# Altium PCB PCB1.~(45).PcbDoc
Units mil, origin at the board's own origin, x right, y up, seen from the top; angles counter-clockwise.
Board outline 6000 x 4000 mil, 2 copper layers (Top Layer, Bottom Layer); 37 components, 28 nets, 157 pads, 81 vias.
Unrouted connection lines stored in the file: 73.
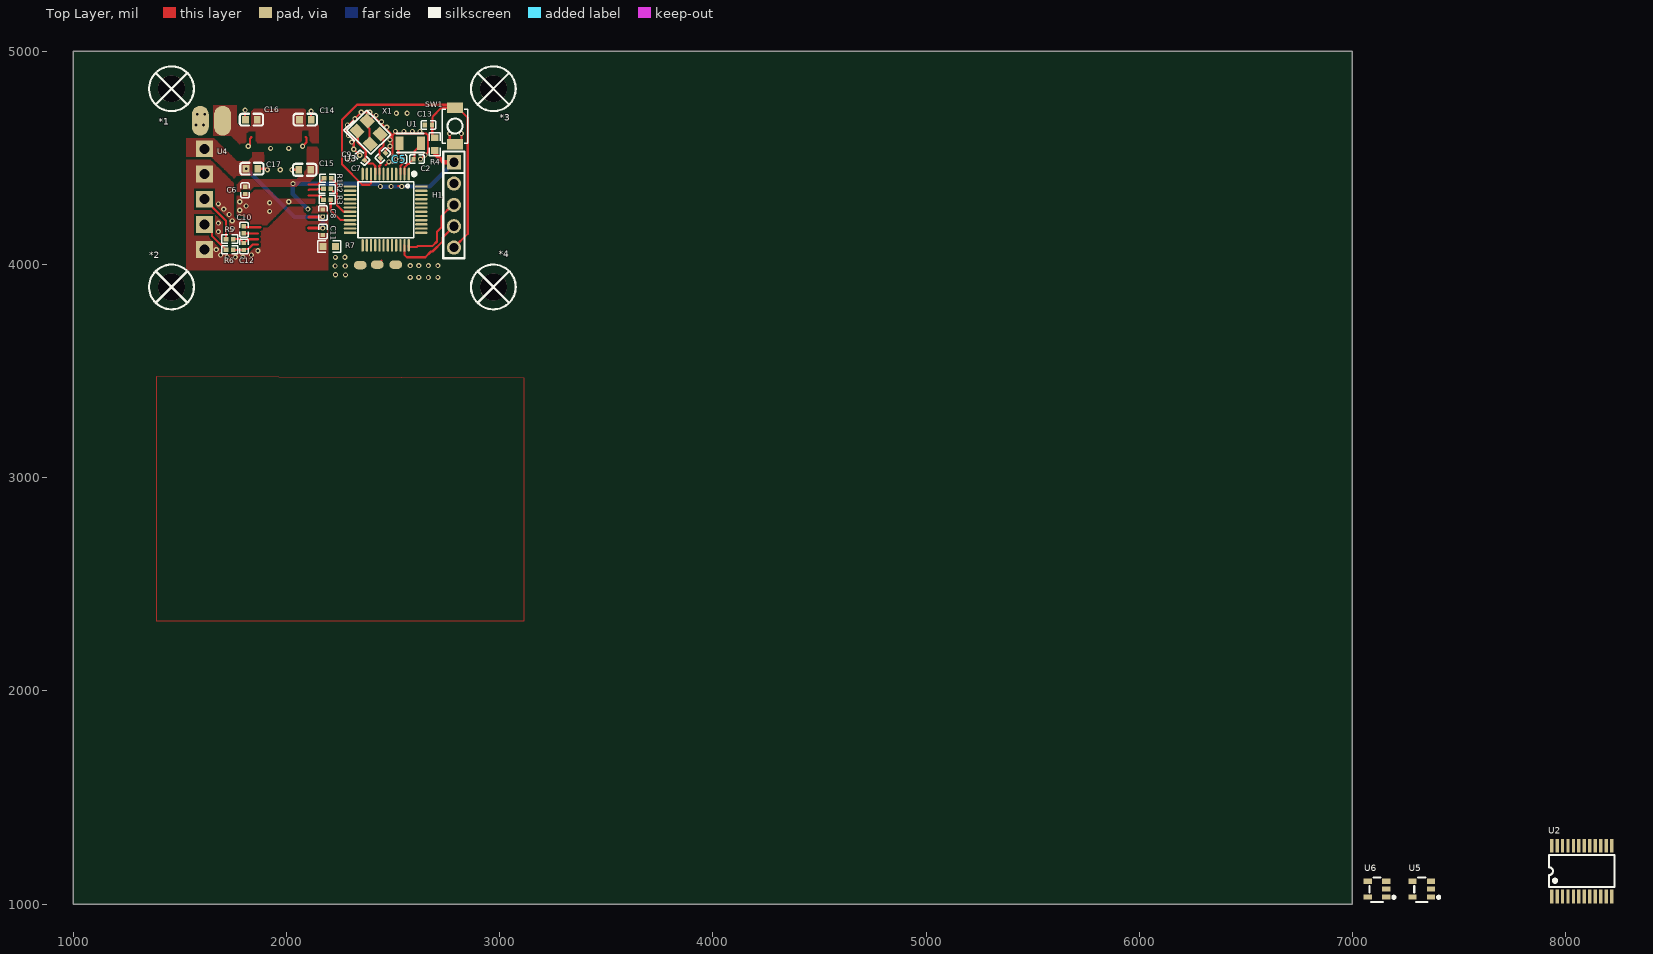
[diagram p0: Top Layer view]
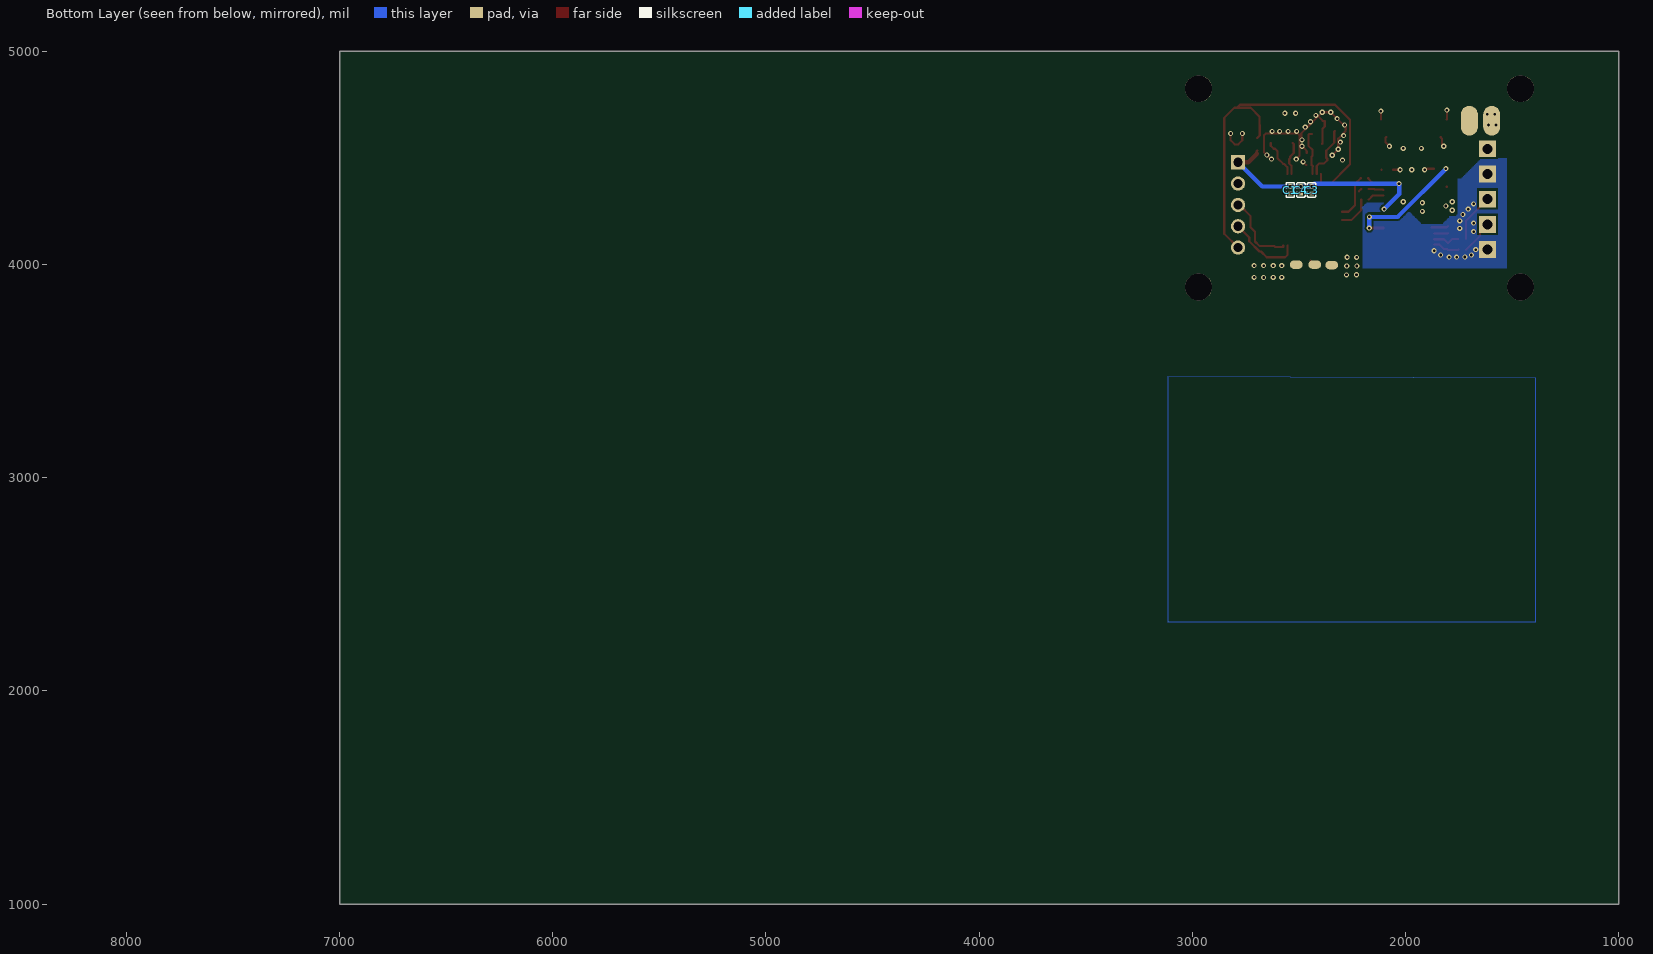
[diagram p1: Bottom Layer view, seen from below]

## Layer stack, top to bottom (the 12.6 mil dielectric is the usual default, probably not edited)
Top Solder: solder mask 0.4, Solder Resist, Dk 3.5
Top Layer: signal copper 1.4
Dielectric 1: dielectric 12.6, FR-4, Dk 4.8
Bottom Layer: signal copper 1.4
Bottom Solder: solder mask 0.4, Solder Resist, Dk 3.5

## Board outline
1000,1000 7000,1000 7000,5000 1000,5000

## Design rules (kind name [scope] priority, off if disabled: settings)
Clearance [All] p1: gap=8 ignorepadtopadclearanceinfootprint=FALSE
ComponentClearance [All] p1: gap=0 collisioncheckmode=3 verticalgap=0 showdistances=FALSE
HoleSize [All] p1: absolutevalues=TRUE maxlimit=130 minlimit=1 maxpercent=80.000 minpercent=20.000
MinimumSolderMaskSliver [All] p1: minsoldermaskwidth=4
PlaneConnect [All] p1: planeconnectstyle=Direct reliefexpansion=20 reliefentries=4 reliefconductorwidth=10 reliefairgap=10
PolygonConnect [All] p1: connectstyle=Direct reliefconductorwidth=10 reliefentries=4 polygonreliefangle="90 Angle" airgapwidth=10
RoutingVias [All] p1: holewidth=28 width=50 viastyle="Through Hole" minholewidth=28 minwidth=50 maxholewidth=28 maxwidth=50
SilkToSilkClearance [All] p1: silktosilkclearance=2
SilkToSolderMaskClearance [IsPad] p1: minsilkscreentomaskgap=2 clearancetoexposedcopper=TRUE
SolderMaskExpansion [All] p1: expansion=0 istentingtop=FALSE
SupplyNets "Schematic Supply Nets_2" [InNet('6V')] p1: voltage=0.000
SupplyNets "Schematic Supply Nets" [InNet('3V3')] p2: voltage=0.000
SupplyNets "Schematic Supply Nets_4" [InNet('5V')] p3: voltage=0.000
SupplyNets "Schematic Supply Nets_3" [InNet('DGND')] p4: voltage=0.000
SupplyNets "Schematic Supply Nets_1" [InNet('AGND')] p5: voltage=0.000
Width [All] p1: maxlimit=50 minlimit=10 preferedwidth=10
24 further rules are at their usual default settings.

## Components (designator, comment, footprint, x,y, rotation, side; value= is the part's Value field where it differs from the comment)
*1 "螺丝孔_1" M3螺丝 1460,4825 r0 top
*2 "螺丝孔_1" M3螺丝 1460,3895 r0 top
*3 "螺丝孔_1" M3螺丝 2970,4825 r0 top
*4 "螺丝孔_1" M3螺丝 2970,3895 r0 top
C1 "cc0402krx7r7bb104" C0402 2540,4350 r270 bottom value=100nF
C2 "cc0402jrnpo9bn220" C0402 2611.54,4495 r180 top value=22pF
C3 "cc0402krx7r7bb104" C0402 2440,4350 r270 bottom value=100nF
C4 "cc0402krx7r7bb104" C0402 2490,4350 r90 bottom value=100nF
C5 "cc0402jrnpo9bn220" C0402 2528.46,4495 r0 top value=22pF
C6 "cc0402krx7r7bb104" C0402 1805,4348.46 r270 top value=100nF
C7 "cc0402jrnpo9bn180" C0402 2451.7,4511.7 r45 top value=18pF
C8 "cc0402krx7r7bb104" C0402 2170,4241.54 r90 top value=100nF
C9 "cc0402jrnpo9bn180" C0402 2354.68,4501.29 r315 top value=18pF
C10 "cc0402krx7r7bb104" C0402 1800,4163.46 r90 top value=100nF
C11 "gcm155r71h103ka55d" C0402 2170,4155 r270 top value=10nF
C12 "gcm155r71h103ka55d" C0402 1800,4085 r270 top value=10nF
C13 "cc0402krx7r7bb104" C0402 2665,4655 r0 top value=100nF
C14 "cga0603x5r105k500jt" C0603 2087.56,4680 r0 top value=1uF
C15 "cga0603x5r105k500jt" C0603 2085,4445 r180 top value=1uF
C16 "cga0603x5r105k500jt" C0603 1835,4680 r180 top value=1uF
C17 "cga0603x5r105k500jt" C0603 1837.44,4450 r0 top value=1uF
H1 "pz254v-11-05p" HDR-TH_5P-P2.54-V-M 2785,4280 r270 top
R1 "frc0402f47r0ts" R0402 2192.04,4405 r0 top value=47Ω
R2 "frc0402f47r0ts" R0402 2190,4355 r0 top value=47Ω
R3 "frc0402f47r0ts" R0402 2190,4305 r0 top value=47Ω
R4 "frc0603f1002ts" R0603 2695,4565 r270 top value=10kΩ
R5 "frc0402f1000ts" R0402 1732.96,4120 r0 top value=100Ω
R6 "frc0402f1000ts" R0402 1732.96,4070 r0 top value=100Ω
R7 "0603waf0000t5e" R0603 2200,4085 r0 top value=0Ω
SW1 "ts-1088-ar02016" SW-SMD_L3.9-W3.0-P4.45 2790,4650 r90 top
U1 "fc31m2-32.768-ntlnndtl" CRYSTAL-SMD_L3.2-W1.5 2580,4570 r0 top value=32.768kHz
U2 "ads1232ipwr" TSSOP-24_L7.8-W4.4-P0.65-LS6.4-BL 8075,1155 r0 top
U3 "stm32g031c8t6" LQFP-48_L7.0-W7.0-P0.50-LS9.0-BL 2464.84,4257.68 r180 top
U4 "5个焊盘" 5个焊盘 1615,4543.1 r270 top
U5 "tps7a2033pdbvr" SOT-23-5_L2.9-W1.6-P0.95-LS2.8-BR 7325,1070 r0 top
U6 "tps7a2050pdbvr" SOT-23-5_L2.9-W1.6-P0.95-LS2.8-BR 7115,1070 r0 top
X1 "x32258mob4si" CRYSTAL-SMD_4P-L3.2-W2.5-BL 2385,4620 r315 top value=8MHz

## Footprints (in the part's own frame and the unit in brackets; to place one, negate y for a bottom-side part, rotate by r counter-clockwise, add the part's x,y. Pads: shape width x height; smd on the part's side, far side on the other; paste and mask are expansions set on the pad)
5个焊盘 [mm]
  rect 2x2 hole 1.2: 1(0,0) 2(3,0) 3(6.001,0) 4(9,0) 5(12,0)
C0402 [mm]
  rect 0.5x0.54 smd: 1(-0.42,0) 2(0.42,0)
  silkscreen extent -0.87,-0.5 0.87,0.5
C0603 [mm]
  rect 0.8x0.9 smd: 1(-0.7,0) 2(0.7,0)
  silkscreen extent -1.39,-0.71 1.39,0.71
CRYSTAL-SMD_4P-L3.2-W2.5-BL [mm]
  rect 1.4x1.2 smd: 1(-1.1,-0.85) 2(1.1,-0.85) 3(1.1,0.85) 4(-1.1,0.85)
  silkscreen extent -2.26,-1.91 2.03,1.68
CRYSTAL-SMD_L3.2-W1.5 [mm]
  rect 0.95x1.6 smd: 1(-1.308,0) 2(1.308,0)
  silkscreen extent -1.6,-1.14 1.6,1.14
HDR-TH_5P-P2.54-V-M [mm]
  rect 1.7x1.7 hole 1.1: 1(-5.08,0)
  round 1.7 hole 1.1: 2(-2.54,0) 3(0,0) 4(2.54,0) 5(5.08,0)
  silkscreen extent -6.35,-1.27 6.35,1.27
LQFP-48_L7.0-W7.0-P0.50-LS9.0-BL [mm]
  oval 0.27x1.5 smd paste+0 mask+0.05: 1(-2.75,-4.25) 2(-2.25,-4.25) 3(-1.75,-4.25) 4(-1.25,-4.25) 5(-0.75,-4.25) 6(-0.25,-4.25) 7(0.25,-4.25) 8(0.75,-4.25) 9(1.25,-4.25) 10(1.75,-4.25) 11(2.25,-4.25) 12(2.75,-4.25) 25(2.75,4.25) 26(2.25,4.25) 27(1.75,4.25) 28(1.25,4.25) 29(0.75,4.25) 30(0.25,4.25) 31(-0.25,4.25) 32(-0.75,4.25) 33(-1.25,4.25) 34(-1.75,4.25) 35(-2.25,4.25) 36(-2.75,4.25)
  oval 1.5x0.27 smd paste+0 mask+0.05: 13(4.25,-2.75) 14(4.25,-2.25) 15(4.25,-1.75) 16(4.25,-1.25) 17(4.25,-0.75) 18(4.25,-0.25) 19(4.25,0.25) 20(4.25,0.75) 21(4.25,1.25) 22(4.25,1.75) 23(4.25,2.25) 24(4.25,2.75) 37(-4.25,2.75) 38(-4.25,2.25) 39(-4.25,1.75) 40(-4.25,1.25) 41(-4.25,0.75) 42(-4.25,0.25) 43(-4.25,-0.25) 44(-4.25,-0.75) 45(-4.25,-1.25) 46(-4.25,-1.75) 47(-4.25,-2.25) 48(-4.25,-2.75)
  silkscreen extent -3.59,-4.46 3.3,3.34
M3螺丝 [mil]
  round 126 hole 126 paste-99999 mask+4: 1(0,0)
  silkscreen extent -105,-105 105,105
R0402 [mm]
  rect 0.566x0.54 smd paste-100 mask+0.051: 1(-0.433,0) 2(0.433,0)
  silkscreen extent -0.94,-0.5 0.94,0.5
R0603 [mil]
  rect 31.75x34.02 smd paste-3937.01 mask+2: 1(-29.66,0) 2(29.66,0)
  silkscreen extent -55,-26 55,26
SOT-23-5_L2.9-W1.6-P0.95-LS2.8-BR [mm]
  rect 1x0.6 smd paste+0 mask+0.05: 1(1.1,-0.95) 2(1.1,0) 3(1.1,0.95) 4(-1.1,0.95) 5(-1.1,-0.95)
  silkscreen extent -0.89,-1.52 2.16,1.4
SW-SMD_L3.9-W3.0-P4.45 [mm]
  rect 1.23x1.86 smd: 1(-2.185,0) 2(2.185,0)
  silkscreen extent -2.03,-1.54 2.03,1.54
TSSOP-24_L7.8-W4.4-P0.65-LS6.4-BL [mm]
  rect 0.4x1.65 smd: 1(-3.575,-3.023) 2(-2.925,-3.023) 3(-2.275,-3.023) 4(-1.625,-3.023) 5(-0.975,-3.023) 6(-0.325,-3.023) 7(0.325,-3.023) 8(0.975,-3.023) 9(1.625,-3.023) 10(2.275,-3.023) 11(2.925,-3.023) 12(3.575,-3.023) 13(3.575,3.023) 14(2.925,3.023) 15(2.275,3.023) 16(1.625,3.023) 17(0.975,3.023) 18(0.325,3.023) 19(-0.325,3.023) 20(-0.975,3.023) 21(-1.625,3.023) 22(-2.275,3.023) 23(-2.925,3.023) 24(-3.575,3.023)
  silkscreen extent -3.89,-1.91 3.94,1.91

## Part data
C1 C3 C4 C6 C8 C10 C13: "容值:100nF;精度:±10%;额定电压:16V;温度系数:X7R;", JLCPCB Part Class="Extended Part", LCSC Part Name="100nF ±10% 16V", Manufacturer=YAGEO(国巨), ManufacturerPart=CC0402KRX7R7BB104, Temperature Coefficient=X7R, Tolerance=±10%, Voltage Rating=16V
C2 C5: "容值:22pF;精度:±5%;额定电压:50V;温度系数:NP0;", JLCPCB Part Class="Extended Part", LCSC Part Name="22pF ±5% 50V", Manufacturer=YAGEO(国巨), ManufacturerPart=CC0402JRNPO9BN220, Temperature Coefficient=NP0, Tolerance=±5%, Voltage Rating=50V
C7 C9: "容值:18pF;精度:±5%;额定电压:50V;温度系数:NP0;", JLCPCB Part Class="Extended Part", LCSC Part Name="18pF ±5% 50V", Manufacturer=YAGEO(国巨), ManufacturerPart=CC0402JRNPO9BN180, Temperature Coefficient=NP0, Tolerance=±5%, Voltage Rating=50V
C11 C12: "容值:10nF;精度:±10%;额定电压:50V;温度系数:X7R;", JLCPCB Part Class="Extended Part", LCSC Part Name="10nF ±10% 50V", Manufacturer=muRata(村田), ManufacturerPart=GCM155R71H103KA55D, Temperature Coefficient=X7R, Tolerance=±10%, Voltage Rating=50V
C14 C15 C16 C17: "容值:1uF;精度:±10%;额定电压:50V;温度系数:X5R;", JLCPCB Part Class="Extended Part", LCSC Part Name="1uF ±10% 50V 停产", Manufacturer=HRE(芯声), ManufacturerPart=CGA0603X5R105K500JT, Temperature Coefficient=X5R, Tolerance=±10%, Voltage Rating=50V
H1: "插针结构:1x5P;间距:2.54mm;行距:-;圆针/方针:方针;安装方式:直插;排数:单排;总PIN位数:5P;额定电流:3A;额定电压:250V;配合针长度:6mm;塑高:2.5mm;端接针长度:3mm;触头材质:黄铜;触头镀层:-;工作温度:-40℃~+105℃;颜色:黑色;", Color=黑色, Current Rating=3A, JLCPCB Part Class="Extended Part", LCSC Part Name="1x5P 间距:2.54mm 方针 直插", Manufacturer=XFCN(兴飞), ManufacturerPart=PZ254V-11-05P, Operating Temperature=-40℃~+105℃, Voltage Rating (Max)=250V
R1 R2 R3: "电阻类型:厚膜电阻;阻值:47Ω;精度:±1%;功率:62.5mW;工作电压:50V;温度系数:±100ppm/℃;", JLCPCB Part Class="Extended Part", LCSC Part Name="47Ω ±1% 62.5mW 厚膜电阻", Manufacturer=FOJAN(富捷), ManufacturerPart=FRC0402F47R0TS, Operating Temperature=-55℃~+155℃, Power(Watts)=62.5mW, Temperature Coefficient=±100ppm/℃, Tolerance=±1%, Voltage-Supply(Max)=50V
R4: "电阻类型:厚膜电阻;阻值:10kΩ;精度:±1%;功率:100mW;工作电压:75V;温度系数:±100ppm/℃;", JLCPCB Part Class="Extended Part", LCSC Part Name="10kΩ ±1% 100mW 厚膜电阻", Manufacturer=FOJAN(富捷), ManufacturerPart=FRC0603F1002TS, Operating Temperature=-55℃~+155℃, Power(Watts)=100mW, Temperature Coefficient=±100ppm/℃, Tolerance=±1%, Voltage-Supply(Max)=75V
R5 R6: "电阻类型:厚膜电阻;阻值:100Ω;精度:±1%;功率:62.5mW;工作电压:50V;温度系数:±100ppm/℃;", JLCPCB Part Class="Extended Part", LCSC Part Name="100Ω ±1% 62.5mW 厚膜电阻", Manufacturer=FOJAN(富捷), ManufacturerPart=FRC0402F1000TS, Operating Temperature=-55℃~+155℃, Power(Watts)=62.5mW, Temperature Coefficient=±100ppm/℃, Tolerance=±1%, Voltage-Supply(Max)=50V
R7: "电阻类型:厚膜电阻;阻值:0Ω;精度:±1%;功率:100mW;工作电压:75V;温度系数:-;", JLCPCB Part Class="Basic Part", LCSC Part Name="0Ω ±1% 100mW 厚膜电阻", Manufacturer=UNI-ROYAL(厚声), ManufacturerPart=0603WAF0000T5E, Operating Temperature=-55℃~+155℃, Power(Watts)=100mW, Temperature Coefficient=-, Tolerance=±1%, Voltage-Supply(Max)=75V
SW1: "电路结构:单刀单掷;按钮形状:圆形按钮;作用力:1.6N;安装方式:立贴;开关长度:3.9mm;开关宽度:3mm;开关高度:2mm;带支架:不带支架;触点电流:50mA;额定电压:12V;带灯:-;工作寿命:10万次;", Actuator/Cap Color=黑色, Contact Current=50mA, IP Rating=-, JLCPCB Part Class="Basic Part", LCSC Part Name="3.9*3*2mm 立贴 轻触开关", Manufacturer=XUNPU(讯普), ManufacturerPart=TS-1088-AR02016, Operating Force=1.6N, Operating Temperature=-30℃~+80℃, Voltage Rating=12V
U1: "晶振类型:贴片晶振;频率:32.768kHz;常温频差:±10ppm;负载电容:12.5pF;频率稳定度:±10ppm;", Equivalent Series Resistance(ESR)=70kΩ, Frequency Stability=±10ppm, JLCPCB Part Class="Extended Part", LCSC Part Name="3215 2P 32.768kHz 12.5pF ±10ppm -40~+85℃(±10ppm)", Load Capacitance=12.5pF, Manufacturer=HCI(杭晶), ManufacturerPart=FC31M2-32.768-NTLNNDTL, Operating Temperature=-40℃~+85℃
U2: "分辨率(位):24;采样率:10Hz;工作电压:2.7V~5.3V;接口类型:SPI;", Clock Frequency=4.9152MHz；200kHz~8MHz, JLCPCB Part Class="Extended Part", LCSC Part Name="用于桥式传感器的24bit 模数转换器", Manufacturer=TI(德州仪器), ManufacturerPart=ADS1232IPWR, Operating Temperature=-40℃~+105℃, Quiescent Current (Iq)=1.3uA, Temperature Sensors=内置, Voltage - Supply=2.7V~5.3V, Voltage Reference=外置, Voltage Reference Drift=-
U3: "CPU内核:ARM Cortex-M0+;CPU最大主频:64MHz;CPU位数:32 Bit;", JLCPCB Part Class="Extended Part", LCSC Part Name="主流Arm Cortex-M0+ MCU，具有64 KB Flash存储器、8 KB RAM、64 MHz CPU、2x USART、定时器、ADC和通信接口，1.7-3.6V", Manufacturer=ST(意法半导体), ManufacturerPart=STM32G031C8T6, Operating Temperature=-40℃~+85℃, Voltage - Supply=1.7V~3.6V
U5: "输出类型:固定;最大输入电压:6V;输出电压:3.3V;输出电流:300mA;输出极性:正极;", Dropout Voltage=140mV@(300mA), JLCPCB Part Class="Extended Part", LCSC Part Name="具有高 PSRR 的 300mA、超低噪声、低 IQ、低压降 (LDO) 线性稳压器", Manufacturer=TI(德州仪器), ManufacturerPart=TPS7A2033PDBVR, Maximum Input Voltage=6V, Operating Temperature=-40℃~+125℃@(Tj), Output Current=300mA, Output Voltage=3.3V, standby current=15uA
U6: "输出极性:正极;工作电压:6V;输出电压:5V;输出电流:300mA;电源纹波抑制比(PSRR):65dB@(100Hz);输出类型:固定;", JLCPCB Part Class="Extended Part", LCSC Part Name="800mV~5.5V 300mA 6V", Manufacturer=TI(德州仪器), ManufacturerPart=TPS7A2050PDBVR, Operating Temperature=-40℃~+125℃@(Tj), Output Current=300mA, Output Voltage=5V, Power Supply Rejection Ratio (PSRR)=65dB@(100Hz), standby current=6.5uA, Voltage - Supply=6V, Voltage Dropout=140mV@(300mA)
X1: "晶振类型:贴片晶振;频率:8MHz;常温频差:±10ppm;负载电容:12pF;频率稳定度:±20ppm;", Equivalent Series Resistance(ESR)=180Ω, Frequency Stability=±20ppm, JLCPCB Part Class="Extended Part", LCSC Part Name="YSX321SL 8MHZ 4P 3225 12PF ±10PPM -40~85℃ (±20PPM)", Load Capacitance=12pF, Manufacturer=YXC(扬兴晶振), ManufacturerPart=X32258MOB4SI, Normal temperature Frequency Tolerance=±10ppm, Operating Temperature=-40℃~+85℃

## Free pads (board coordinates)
  oval 80x140 all layers, no hole: 7(1595,4675) 7(1700,4675)
  oval 60x40 all layers, no hole: 7(2345.3,3998) 7(2425,4000) 7(2512,3999.83)

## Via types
v1: diameter 24, hole 12, Top Layer to Bottom Layer, tented both sides, 81 vias

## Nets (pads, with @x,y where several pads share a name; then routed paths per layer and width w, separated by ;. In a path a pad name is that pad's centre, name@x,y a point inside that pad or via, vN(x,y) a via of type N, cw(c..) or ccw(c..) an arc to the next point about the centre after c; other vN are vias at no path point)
3V3: C1.1 C3.1 C4.2 C6.1 C15.1 H1.1 R4.2 U2.1 U2.19 U2.20 U3.4 U3.5 U3.6 U5.5 | length 1103.6
  Top Layer w10: C6.1 C6.1@1805.79,4365 ; C15.1@2112.56,4443.03 C15.1 ; v1(2440,4366.54) v1@2442.68,4369.22 ; 2521.89,4369.22 2537.32,4369.22 v1(2540,4366.54) ; R4.2 2697.01,4533.33 R4.2@2697.01,4519.53
  Top Layer w20: R4.2@2697.01,4519.53 2736.54,4480 H1.1
  Bottom Layer w10: v1@2028.6,4378.6 v1(2030,4380) ; 2058.74,4380 2060.53,4378.21
  Bottom Layer w20: v1@2028.6,4378.6 2028.6,4331.4 v1(2100,4260) ; v1@2030.11,4379.89 2426.18,4379.89 C3.1@2439.37,4366.7 ; C3.1@2440.69,4365.85 C4.2@2489.31,4365.85 ; C4.2@2490.63,4366.49 C1.1@2539.37,4366.49 ; v1(2540,4366.54) 2671.54,4366.54 H1.1
  other v1: 2490,4366.54
5V: C8.1 C11.1 C17.1 U2.16 U2.18 U4.1 U6.5 | length 638.5
  Top Layer w10: 2104,4171.02 2104.26,4171.28 ; 2104,4222.21 2105.39,4223.6 ; v1(2168.61,4223.6) C8.1 ; v1(2169.74,4171.28) C11.1
  Top Layer w15: 2104.26,4171.28 v1(2169.74,4171.28) ; 2105.39,4223.6 v1(2168.61,4223.6)
  Bottom Layer w10: v1(2168.61,4223.6) v1@2169.17,4223.04 ; v1@2169.17,4171.85 v1(2169.74,4171.28)
  Bottom Layer w20: v1(1810,4450) 2036.39,4223.6 v1(2168.61,4223.6) ; v1@2169.17,4171.85 v1@2169.17,4223.04
6V: C14.1 C16.1 pad.7@1700,4675 U5.1 U5.3 U6.1 U6.3
AGND: C8.2 C11.2 R7.1 U2.13 U2.14 U2.15 U2.17 U4.2 U4.5
  other v1: 1760,4035 1795,4035 1720.87,4035.63 1690,4045 1835,4045 1865,4065 1670,4070 1680,4155 1745,4170 1680,4195 1745,4205 1730,4235 1705,4260 1680,4285
AINN1: R6.1 U4.4 | length 160.9
  Top Layer w10: U4.4 1649.37,4154.39 1649.37,4136.04 1715.41,4070 R6.1
AINP1: R5.1 U4.3 | length 228.7
  Top Layer w10: U4.3 1715.92,4205.94 R5.1
DGND: C1.2 C2.1 C3.2 C4.1 C5.1 C6.2 C7.2 C9.1 C13.1 C14.2 C15.2 C16.2 C17.2 H1.2 pad.7@1595,4675 pad.7@2345.3,3998 R7.2 SW1.1 U2.2 U2.3 U2.4 U2.5 U2.6 U2.7 U2.8 U2.21 U3.7 U5.2 U6.2 X1.2 X1.4 | length 1384
  Top Layer w10: v1(1805,4725) 1805,4682.44 C16.2 ; C17.2 1901.21,4450 1906.21,4445 v1(1910,4445) ; v1(2025,4445) C15.2 ; v1(2115,4720) 2115.12,4719.88 C14.2 ; v1(2342.98,4512.98) v1(2315,4540.96) 2315,4590.88 2281.52,4624.36 2281.52,4633.48 2280,4635 2280,4645 v1(2350,4715) v1(2390,4715) v1@2409.14,4695.86 ; X1.2 2389.18,4568.5 2389.18,4636.81 2378.04,4647.95 X1.4 2387.57,4674.29 v1@2409.14,4695.86 ; C7.2 2462.83,4523.95 2462.83,4530.8 2463.39,4531.35 2463.39,4533.39 v1(2485,4555) ; v1(2485,4585) 2487.68,4587.68 2487.68,4604.07 2488.48,4604.87 2488.48,4615.64 2457.06,4647.06 2457.06,4647.94 v1@2409.14,4695.86 ; v1(2511.92,4495) 2511.92,4495.79 2496.8,4510.91 2496.8,4606.88 2505.36,4615.44 2649.41,4615.44 2650.35,4614.5 2655.59,4614.5 2663.2,4606.88 2663.2,4527.61 v1(2649.71,4514.12) 2636.22,4500.63 2632.92,4500.63 C2.1@2628.08,4495.79 ; v1(2765,4615) 2765,4583.19 2784.21,4563.98 SW1.1 2800.79,4563.98 2820,4583.19 v1(2820,4615)
  other v1: 2580,3940 2620,3940 2665.24,3939.54 2710,3940 2229.44,3952.22 2276.16,3951.9 2227.87,3993.61 2274.91,3993.61 2580,3995 2620,3995 2665,3995 2710,3995 2228.81,4034.06 2273.34,4034.38 1920,4250 1780,4255 1810,4275 1920,4290 1780,4295 2010,4295 1970,4445 2295,4490 2628.08,4495 1925,4545 2010,4545 2305,4575 2290,4605 2510,4625 2550,4625 2590,4625 2625,4625 2470,4645 1575,4655 1610,4655 2285,4655 2445,4670 2320,4685 2420,4700 1580,4705 1615,4705 2515,4710 2565,4710
DOUT: R1.2 U3.19 | length 211.9
  Top Layer w10: R1.2 2209.59,4405 2236.17,4378.41 2236.17,4278.76 2266.97,4247.96 2297.4,4247.96 U3.19
NetC2_2: C2.2 U1.2 U3.2 | length 183.5
  Top Layer w10: U3.2 2553.54,4425.12 2553.54,4456.49 2569.61,4472.56 2573.35,4472.56 2599.84,4499.06 2599.84,4532.3 2611.05,4543.5 2617.8,4543.5 2631.5,4557.21 U1.2
NetC5_2: C5.2 U1.1 U3.3 | length 160.6
  Top Layer w10: U1.1 2523.5,4565 2523.5,4523.5 2540.16,4506.85 2540.16,4499.84 C5.2 2545,4473.85 2533.86,4462.71 2533.86,4425.12 U3.3
NetC7_1: C7.1 U3.8 X1.3 | length 214.9
  Top Layer w10: U3.8 U3.8 2435.35,4432.44 2435.35,4459.95 2434.11,4461.19 2440.56,4467.63 2440.56,4506.29 2435.91,4510.93 2435.91,4538.56 2455.11,4557.75 2455.11,4609.54 2452.33,4612.33 2440,4612.33 X1.3
NetC9_2: C9.2 U3.9 X1.1 | length 254.5
  Top Layer w10: X1.1 2333.5,4624.18 2333.5,4572.39 2371.34,4534.54 2371.34,4501.41 2366.37,4496.44 C9.2 2381.12,4474.85 2403.69,4474.85 2415.67,4462.86 2415.67,4432.44 2415.67,4425.04 U3.9
NetC10_1: C10.1 U2.10 | length 66.6
  Top Layer w10: C10.1 1800.74,4146.18 1865.26,4146.18 1866,4145.43
NetC10_2: C10.2 U2.9 | length 78.3
  Top Layer w10: C10.2 1804.84,4175.16 1819.84,4175.16 1820,4175 1876.23,4175
NetC12_1: C12.1 R5.2 U2.11 | length 131.2
  Top Layer w10: R5.2 1780.75,4120 1799.21,4101.54 C12.1 1800.79,4101.54 1818.52,4119.27 1865.43,4119.27 1866,4119.84
NetC12_2: C12.2 R6.2 U2.12 | length 127.3
  Top Layer w10: R6.2 1750.77,4069.23 1799.23,4069.23 C12.2 1804.84,4073.3 1820.44,4073.3 1841.39,4094.26 1866,4094.26
NetR1_1: R1.1 U2.24 | length 83.4
  Top Layer w10: 2104,4375.74 2145.74,4375.74 2168.86,4398.86 2168.86,4399.37 2174.49,4405 R1.1
NetR2_1: R2.1 U2.23 | length 71
  Top Layer w10: 2104,4350.15 2106.87,4353.02 2144.85,4353.02 2146.82,4355 R2.1
NetR3_1: R3.1 U2.22 | length 77.1
  Top Layer w10: 2104,4324.56 2152.89,4324.56 2172.45,4305 R3.1
NRST: C13.2 H1.5 R4.1 SW1.2 U3.10 | length 1940.1
  Top Layer w10: U3.10 2396.06,4424.88 2396.06,4384.31 2396.1,4384.27 2394.62,4382.79 2394.62,4381.29 2388.25,4374.91 2355.11,4374.91 2260,4470.02 2260,4679.63 2330.22,4749.85 2776.17,4749.85 SW1.2 ; C13.2 C13.2@2681.54,4655.79 ; R4.1 2693.87,4594.66 2682.99,4605.54 2682.99,4652.99 2685,4655 2685,4695 2726.02,4736.02 SW1.2 ; H1.5 2850,4145 2850,4688.42 2802.4,4736.02 SW1.2
PDWN: R3.2 U3.21 | length 159.4
  Top Layer w10: R3.2 2207.04,4255.66 2254.11,4208.59 2297.4,4208.59 U3.21
SCLK: R2.2 U3.20 | length 15.5
  Top Layer w10: R2.2 2207.55,4355 R2.2@2218.17,4344.37
SWCLK: H1.3 U3.36 | length 359.3
  Top Layer w10: U3.36 2573.11,4082.84 2573.27,4082.68 2610.66,4082.68 2615.66,4087.68 2685.04,4087.68 2705.45,4108.09 2705.45,4153.76 2725.86,4174.17 2725.86,4227.64 2778.22,4280 H1.3
SWDIO: H1.4 U3.35 | length 352.4
  Top Layer w10: U3.35 2553.3,4090.24 2553.3,4047.61 2552.35,4046.66 2564.33,4034.67 2650.57,4034.67 2677.48,4061.59 2684.4,4061.59 2732.47,4109.65 2732.47,4127.47 H1.4
USART1_RX: pad.7@2512,3999.83 U3.32
USART1_TX: pad.7@2425,4000 U3.29
USART2_RX: U3.14
USART2_TX: U3.13
pads on no net: *1.1 *2.1 *3.1 *4.1 U3.1 U3.11 U3.12 U3.15 U3.16 U3.17 U3.18 U3.22 U3.23 U3.24 U3.25 U3.26 U3.27 U3.28 U3.30 U3.31 U3.33 U3.34 U3.37 U3.38 U3.39 U3.40 U3.41 U3.42 U3.43 U3.44 U3.45 U3.46 U3.47 U3.48 U5.4 U6.4
copper on no net: | length 164.1
  Top Layer w10: v1(1820,4555) 1828.62,4563.62 1828.62,4591.92 1835.01,4598.31 ; v1(2075,4555) 2092.68,4572.68 2092.68,4595.63 2090.01,4598.31 ; 2425,4000 2426.88,4000 2445.47,4018.59 ; 2465.16,4466.85 v1(2480,4481.69) v1@2480,4485 ; 2504.65,4007.18 2512,3999.83

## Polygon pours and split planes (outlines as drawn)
DGND on Top Layer "NONET_L-01_P-001" (hatched Horizontal grid 4 track 5, remove dead copper, pour order 15): 1389.4,3473.32 1389.4,2330.12 3114.4,2330.12 3114.4,3466.93
5V on Top Layer "NONET_L-01_P-001" (hatched Horizontal grid 4 track 5, remove dead copper, pour order 9): 1893.57,4530 1873.57,4530 1838.57,4530 1838.57,4505 1818.57,4485 1768.57,4485 1658.57,4595 1528.57,4595 1528.57,4505 1645,4505 1680,4475 1753.57,4405 1768.57,4420 1838.57,4420 1838.57,4480 1843.57,4485 1848.57,4480 1895,4480
AGND on Top Layer "NONET_L-01_P-001" (hatched Horizontal grid 4 track 5, remove dead copper, pour order 7): 1565,4495 1640,4495 1755,4380 1755,4225 1795,4225 1827.5,4192.5 1907.5,4192.5 1915,4185 2010,4280 2180,4280 2185,4285 2195,4275 2195,3975 2180,3975 2160,3975 1530,3975 1530,4495
DGND on Top Layer "NONET_L-01_P-001" (hatched Horizontal grid 4 track 5, remove dead copper, pour order 5): 1765,4340 1820,4340 1832.5,4352.5 1830,4355 1830,4365 1905,4365 1960,4310 2135,4310 2135,4290 2130,4285 2005,4285 1905,4185 1830,4185 1830,4200 1800,4230 1765,4230
6V on Top Layer "NONET_L-01_P-001" (hatched Horizontal grid 4 track 5, remove dead copper, pour order 3): 1655,4750 1655,4605 1740,4605 1780,4565 1785,4570 1810,4570 1810,4615 1820,4625 1855,4625 1855,4580 1865,4570 2070,4570 2070,4625 2075,4630 2105,4630 2105,4585 2120,4570 2150,4570 2150,4655 2140,4665 2090,4665 2090,4725 2080,4735 1850,4735 1835,4720 1835,4650 1780,4650 1765,4665 1765,4750
3V3 on Top Layer "NONET_L-01_P-001" (hatched Horizontal grid 4 track 5, remove dead copper, pour order 2): 2095,4555 2095,4450 2045,4400 1790,4400 1765,4375 1765,4340 1820,4340 1845,4365 2045,4365 2070,4390 2110,4390 2150,4430 2150,4545 2140,4555
DGND on Bottom Layer "NONET_L-01_P-001" (hatched Horizontal grid 4 track 5, remove dead copper, pour order 16): 3114.4,3473.32 3114.4,2325.12 1389.4,2325.12 1389.4,3466.93
AGND on Bottom Layer "NONET_L-01_P-001" (hatched Horizontal grid 4 track 5, remove dead copper, pour order 12): 1525,4500 1640,4500 1740,4400 1755,4400 1755,4235 1765,4225 1795,4225 1795,4220 1825,4190 1925,4190 2025,4290 2180,4290 2205,4265 2200,4260 2200,3980 1525,3980

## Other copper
Top Layer:
  pour cut-out: 2275,4655 2350,4730 2350,4735 2390,4735 2485,4640 2485,4635 2495,4625 2510,4640 2630.08,4640 2665,4605.08 2665,4510 2630,4475 2490,4475 2445,4520 2415,4490 2335,4490 2295,4530 2300,4535 2300,4580 2265,4615 2270,4620 2270,4660

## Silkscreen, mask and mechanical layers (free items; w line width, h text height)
Mechanical 1:
  lines w10: 1345,3775 3085,3775 3085,4930 1345,4930 1345,3775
